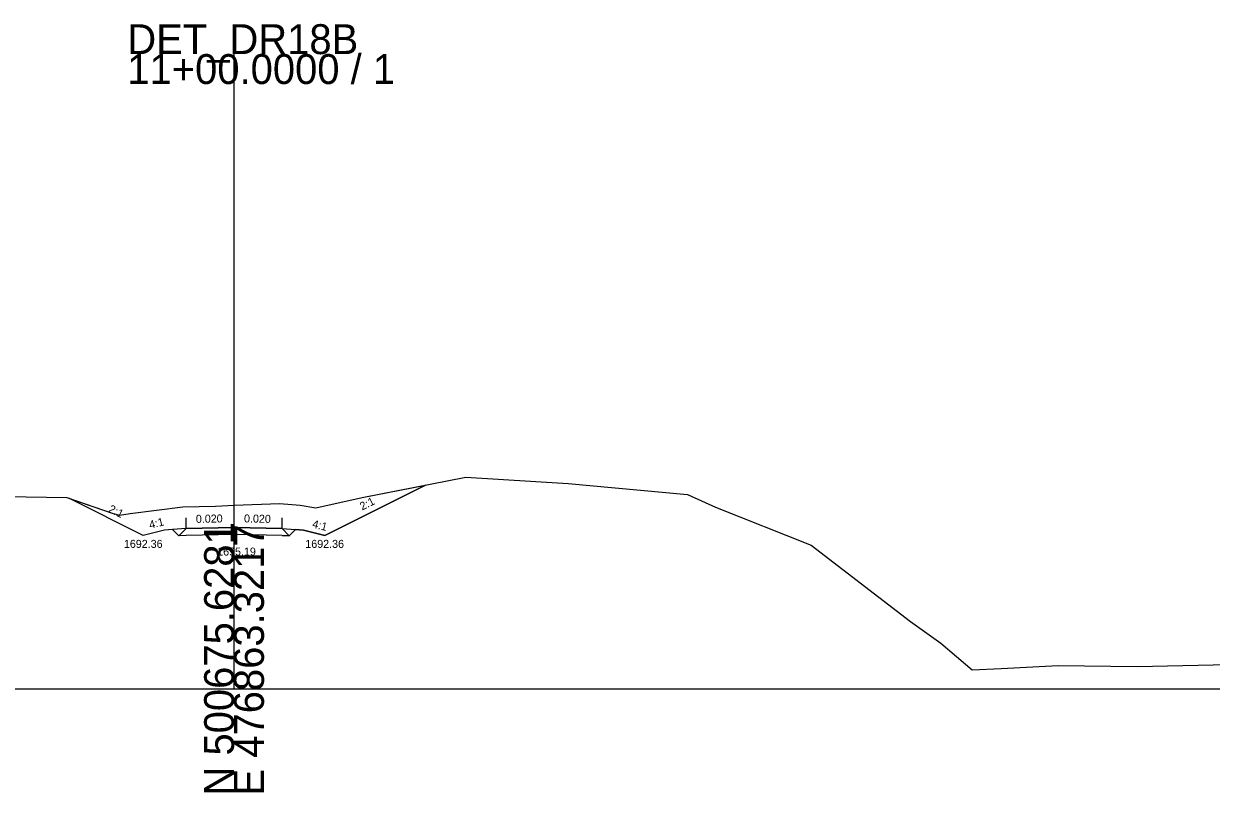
# Model space of a CAD drawing. Extents: x -26 to 403, y -10 to 2570.
# Drawn here: x 180.3 to 291.6, y 1990.3 to 2062.3 of the extents above; entities that cross this region are included whole.
import ezdxf

# ---------------------------------------------------------------- set-up
doc = ezdxf.new("R2010")
doc.units = 0
for name, color, linetype in [('Exist Cross Section Cell', 7, 'Continuous'), ('Exist XS Center Line Elevation Label', 7, 'Continuous'), ('Exist XS Ground Line', 7, 'Continuous'), ('Prop XS Ditch Slope Text', 7, 'Continuous'), ('Prop XS Ditch Standard Text', 7, 'Continuous'), ('Prop XS Dump Level', 7, 'Continuous'), ('Prop XS Earthwork Shape', 7, 'Continuous'), ('Prop XS EOT Tick Mark', 7, 'Continuous'), ('Prop XS Finish Grade', 7, 'Continuous'), ('Prop XS Finish Grade Earthwork', 7, 'Continuous'), ('Prop XS Finish Grade Pavement', 7, 'Continuous'), ('Prop XS Hydro Typical Ditch Data', 7, 'Continuous'), ('Prop XS Pvmt Edge Slope', 7, 'Continuous'), ('Prop XS SE Text', 7, 'Continuous'), ('Prop XS Shoulder Borrow Shape', 7, 'Continuous'), ('Prop XS Side Slope Text', 7, 'Continuous'), ('Prop XS Subgrade Earthwork', 7, 'Continuous')]:
    doc.layers.add(name, color=color, linetype=linetype)

msp = doc.modelspace()

# ---------------------------------------------------------------- linework, layer by layer
at = {"layer": 'Exist Cross Section Cell'}
for p, q in [((200, 2000), (200, 2059.46)), ((0, 2000), (200, 2000)), ((200, 2000), (400, 2000))]:
    msp.add_line(p, q, dxfattribs=at)
at = {"layer": 'Exist XS Ground Line'}
msp.add_lwpolyline([(172.84, 2018.11), (184.33, 2017.91), (188.68, 2016.42), (189.26, 2016.27), (190.28, 2016.43), (195.2, 2017.04), (198.25, 2017.11), (200, 2017.19), (204.25, 2017.37), (206.19, 2017.21), (207.66, 2016.96), (212.02, 2017.93), (221.73, 2019.82), (231.3, 2019.22), (242.49, 2018.21), (245.11, 2017.03), (254.09, 2013.44), (263.39, 2006.3), (266.23, 2004.28), (269.18, 2001.78), (271.89, 2001.89), (277.22, 2002.19), (284.64, 2002.1), (293.17, 2002.29)], dxfattribs=at)
at = {"layer": 'Prop XS Dump Level'}
for p, q in [((200, 2015.11), (195.5, 2015.02)), ((195.5, 2015.02), (200, 2015.11)), ((204.5, 2015.02), (200, 2015.11)), ((200, 2015.11), (204.5, 2015.02))]:
    msp.add_line(p, q, dxfattribs=at)
at = {"layer": 'Prop XS Earthwork Shape'}
msp.add_lwpolyline([(195.5, 2014.36), (194.82, 2014.34), (194.24, 2014.92), (193.5, 2014.86), (191.5, 2014.36), (184.58, 2017.82), (188.68, 2016.42), (189.26, 2016.27), (190.28, 2016.43), (195.2, 2017.04), (198.25, 2017.11), (200, 2017.19), (204.25, 2017.37), (206.19, 2017.21), (207.66, 2016.96), (212.02, 2017.93), (217.94, 2019.08), (208.5, 2014.36), (206.5, 2014.86), (205.76, 2014.92), (205.18, 2014.34), (204.5, 2014.36), (200, 2014.45)], close=True, dxfattribs=at)
at = {"layer": 'Prop XS EOT Tick Mark'}
for p, q in [((195.5, 2015.02), (195.5, 2016.02)), ((204.5, 2015.02), (204.5, 2016.02))]:
    msp.add_line(p, q, dxfattribs=at)
at = {"layer": 'Prop XS Finish Grade'}
for p, q in [((195.5, 2015.02), (194.24, 2014.92)), ((204.5, 2015.02), (205.76, 2014.92))]:
    msp.add_line(p, q, dxfattribs=at)
at = {"layer": 'Prop XS Finish Grade Earthwork'}
for p, q in [((208.5, 2014.36), (217.94, 2019.08)), ((191.5, 2014.36), (184.58, 2017.82)), ((193.5, 2014.86), (191.5, 2014.36)), ((194.24, 2014.92), (193.5, 2014.86)), ((205.76, 2014.92), (206.5, 2014.86)), ((206.5, 2014.86), (208.5, 2014.36))]:
    msp.add_line(p, q, dxfattribs=at)
at = {"layer": 'Prop XS Finish Grade Pavement'}
for p, q in [((195.5, 2015.02), (200, 2015.11)), ((200, 2015.11), (204.5, 2015.02))]:
    msp.add_line(p, q, dxfattribs=at)
at = {"layer": 'Prop XS Hydro Typical Ditch Data'}
for p, q in [((208.5, 2014.36), (217.94, 2019.08)), ((191.5, 2014.36), (184.58, 2017.82)), ((193.5, 2014.86), (191.5, 2014.36)), ((206.5, 2014.86), (208.5, 2014.36))]:
    msp.add_line(p, q, dxfattribs=at)
at = {"layer": 'Prop XS Pvmt Edge Slope'}
for p, q in [((195.5, 2015.02), (194.82, 2014.34)), ((204.5, 2015.02), (205.18, 2014.34))]:
    msp.add_line(p, q, dxfattribs=at)
at = {"layer": 'Prop XS Shoulder Borrow Shape'}
for points in [[(195.5, 2015.02), (194.24, 2014.92), (194.82, 2014.34)], [(204.5, 2015.02), (205.76, 2014.92), (205.18, 2014.34)]]:
    msp.add_lwpolyline(points, close=True, dxfattribs=at)
at = {"layer": 'Prop XS Subgrade Earthwork'}
for p, q in [((194.82, 2014.34), (194.24, 2014.92)), ((195.5, 2014.36), (194.82, 2014.34)), ((200, 2014.45), (195.5, 2014.36)), ((204.5, 2014.36), (200, 2014.45)), ((204.5, 2014.36), (205.18, 2014.34)), ((205.18, 2014.34), (205.76, 2014.92))]:
    msp.add_line(p, q, dxfattribs=at)

# ---------------------------------------------------------------- texts
at = {"layer": 'Exist Cross Section Cell'}
for s, p in [('DET_DR18B', (190, 2059.46)), ('11+00.0000 / 1', (190, 2056.66))]:
    msp.add_text(s, height=2.8, dxfattribs=at).set_placement(p)
for s, p in [('N 500675.6281', (200, 1990)), ('E 476863.3217', (202.8, 1990))]:
    msp.add_text(s, height=2.8, rotation=90, dxfattribs=at).set_placement(p)
at = {"layer": 'Exist XS Center Line Elevation Label'}
msp.add_text('1695.19', height=0.75, dxfattribs=at).set_placement((198.42, 2012.48))
at = {"layer": 'Prop XS Ditch Slope Text'}
for rotation, p in [(14.0362, (192.14, 2014.98)), (345.9638, (207.28, 2015.12))]:
    msp.add_text('4:1', height=0.75, rotation=rotation, dxfattribs=at).set_placement(p)
at = {"layer": 'Prop XS Ditch Standard Text'}
for p in [(189.68, 2013.2), (206.68, 2013.2)]:
    msp.add_text('1692.36', height=0.75, dxfattribs=at).set_placement(p)
at = {"layer": 'Prop XS Dump Level'}
for p in [(193.5, 2014.82), (206.5, 2014.82)]:
    msp.add_text('Case1', height=0.04, dxfattribs=at).set_placement(p)
at = {"layer": 'Prop XS SE Text'}
for rotation, p in [(1.1458, (196.43, 2015.54)), (358.8542, (200.93, 2015.59))]:
    msp.add_text('0.020', height=0.75, rotation=rotation, dxfattribs=at).set_placement(p)
at = {"layer": 'Prop XS Side Slope Text'}
for rotation, p in [(26.5651, (212.01, 2016.7)), (333.4349, (188.17, 2016.61))]:
    msp.add_text('2:1', height=0.75, rotation=rotation, dxfattribs=at).set_placement(p)

doc.saveas('drawing.dxf')
